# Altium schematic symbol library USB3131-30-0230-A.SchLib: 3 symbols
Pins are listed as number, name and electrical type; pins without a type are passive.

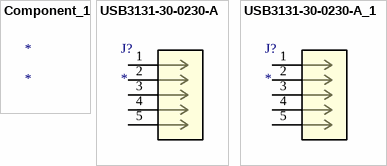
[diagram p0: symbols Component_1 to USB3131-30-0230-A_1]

## Component_1
designator *

## USB3131-30-0230-A
designator J?
No Description Available; Mfr_Name: Global Connector Technology
footprint CONN_USB3131-30-0230-A_GCT
pins: 1, 2, 3, 4, 5

## USB3131-30-0230-A_1
designator J?
No Description Available; Mfr_Name: Global Connector Technology
footprint CONN_USB3131-30-0230-A_GCT
pins: 1, 2, 3, 4, 5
